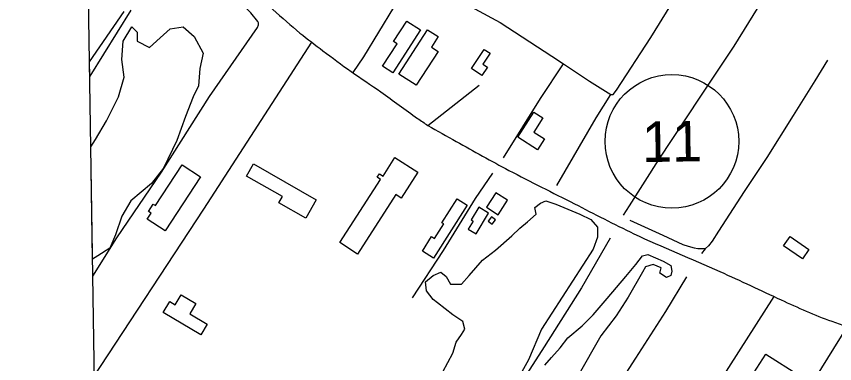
# Model space of a CAD drawing. Extents: x 3855477 to 3893699, y 299188 to 325115.
# Drawn here: x 3859445 to 3861465, y 310674 to 311532 of the extents above; entities that cross this region are included whole.
import ezdxf

# ---------------------------------------------------------------- set-up
doc = ezdxf.new("R2010")
doc.units = 0
for name, color, linetype in [('V-BLDG-OTLN', 7, 'Continuous'), ('V-GRID-FRAM', 7, 'Continuous'), ('V-ROAD-CNTR', 7, 'Continuous'), ('V-ROAD-IDEN', 7, 'Continuous'), ('V-SITE-VEGE', 7, 'Continuous'), ('V-TOPO-SHOR', 7, 'Continuous')]:
    doc.layers.add(name, color=color, linetype=linetype)

msp = doc.modelspace()

# ---------------------------------------------------------------- linework, layer by layer
at = {"layer": 'V-BLDG-OTLN'}
for points in [[(3860442.9, 311498.5), (3860374.1, 311392.1), (3860348.8, 311408.5), (3860384.9, 311464.3), (3860376.5, 311469.7), (3860409.2, 311520.3)], [(3860460.3, 311498.9), (3860486.7, 311481.9), (3860469.8, 311455.7), (3860486.2, 311445.2), (3860432.4, 311361.5), (3860389.6, 311389)], [(3860568.2, 311403.1), (3860599.6, 311450.3), (3860614.4, 311440.5), (3860596.6, 311413.8), (3860608, 311406.1), (3860594.4, 311385.7)], [(3860682.8, 311233.4), (3860722.1, 311295.2), (3860744.4, 311281), (3860722.2, 311246.1), (3860749, 311229), (3860731.9, 311202.1)], [(3860243.6, 310972.9), (3860344.1, 311129.2), (3860336.1, 311134.3), (3860341.7, 311143.1), (3860350.5, 311137.4), (3860379.8, 311182.9), (3860435.9, 311146.8), (3860394.8, 311082.9), (3860381.5, 311091.5), (3860287.2, 310944.9)], [(3859854.4, 311165.3), (3859899.7, 311135.8), (3859812.7, 311002.2), (3859768.3, 311031.1), (3859778, 311046), (3859771.7, 311050), (3859783.3, 311067.8), (3859788.7, 311064.3)], [(3860030.4, 311167.4), (3860185.6, 311078.9), (3860159.8, 311033.6), (3860093.4, 311071.5), (3860102, 311086.6), (3860013.2, 311137.3)], [(3860628.8, 311096), (3860606, 311060.3), (3860634.7, 311041.9), (3860657.5, 311077.7)], [(3860557.7, 311065.1), (3860474.8, 310934.4), (3860447.3, 310951.8), (3860470.2, 310987.8), (3860477.6, 310983.1), (3860500.4, 311019), (3860495.6, 311021.9), (3860532.9, 311080.8)], [(3860580.1, 310994.3), (3860610.9, 311046.1), (3860586.6, 311060.6), (3860567.8, 311029), (3860572.6, 311026.1), (3860560.6, 311006)], [(3860617.7, 311036.9), (3860609.7, 311026.4), (3860619.7, 311018.7), (3860627.7, 311029.2)], [(3861355.3, 310988.4), (3861401.5, 310955.7), (3861385.2, 310932.7), (3861339, 310965.4)], [(3859900.5, 310745.2), (3859807.8, 310800.1), (3859824, 310827.5), (3859837.5, 310819.5), (3859852, 310844.1), (3859888.6, 310822.5), (3859873.5, 310796.9), (3859916.2, 310771.6)], [(3861251, 310628.7), (3861294.9, 310697.6), (3861377.9, 310644.8), (3861333.9, 310575.6), (3861306.7, 310592.9), (3861291.5, 310569.1), (3861316.4, 310553.3), (3861305.3, 310535.8), (3861222.7, 310588.5), (3861234.3, 310606.7), (3861263.2, 310588.3), (3861278, 310611.6)]]:
    msp.add_lwpolyline(points, close=True, dxfattribs=at)
at = {"layer": 'V-GRID-FRAM'}
msp.add_lwpolyline([(3859445.3, 322797), (3891292.6, 323315.8), (3891596.8, 305135.9), (3859733.6, 304616.8), (3859445.3, 322797)], dxfattribs=at)
at = {"layer": 'V-ROAD-CNTR'}
for points in [[(3860276.2, 311393.5), (3860303, 311432.2), (3860377, 311553.8)], [(3860173.8, 311468), (3859907.5, 311055.6), (3859634.7, 310640.5)], [(3860461, 311262.2), (3860587.7, 311361.9)], [(3861315, 310839.8), (3861077.7, 310468.9)], [(3861496.1, 310765.8), (3861268, 310398.5), (3861240.4, 310360.1)]]:
    msp.add_lwpolyline(points, dxfattribs=at)
for points in [[(3859613.3, 311989.2), (3859816.5, 311793.7), (3859931.5, 311684.6), (3860011.9, 311608.3), (3860078.7, 311548.6), (3860145.2, 311490.6), (3860201.9, 311446.9), (3860271.3, 311395.8), (3860344.7, 311345.3), (3860435.6, 311279.7), (3860461, 311262.2)], [(3860461, 311262.2), (3860530.9, 311222.9), (3860661, 311151.4), (3860822.5, 311069), (3860969.5, 310994.9), (3861181.8, 310901.5), (3861332.6, 310831.7), (3861457.8, 310778.8), (3861532.1, 310756.1), (3861622.4, 310736.1), (3861704.6, 310721.1), (3861785.7, 310710.4), (3861858.8, 310704.3)]]:
    msp.add_spline(points, degree=3, dxfattribs=at)
at = {"layer": 'V-ROAD-IDEN'}
msp.add_circle((3861063.1, 311222.9), 165, dxfattribs=at)
msp.add_circle((3861063.1, 311222.9), 165, dxfattribs=at)
at = {"layer": 'V-SITE-VEGE'}
for p, q in [((3859727.5, 311546.7), (3859626.3, 311384.1)), ((3859625.7, 311419.7), (3859711.3, 311544)), ((3859708.6, 311470.9), (3859730.2, 311506.1)), ((3859730.2, 311506.1), (3859743.8, 311492.6)), ((3859824.9, 311500.7), (3859857.3, 311506.1)), ((3859857.3, 311506.1), (3859884.4, 311481.8)), ((3859743.8, 311492.6), (3859743.8, 311470.9)), ((3859800.5, 311479.1), (3859824.9, 311500.7)), ((3859705.9, 311425), (3859708.6, 311470.9)), ((3859743.8, 311470.9), (3859773.5, 311454.7)), ((3859773.5, 311454.7), (3859800.5, 311479.1)), ((3859884.4, 311481.8), (3859906, 311441.2)), ((3859711.3, 311381.7), (3859705.9, 311425)), ((3859906, 311441.2), (3859897.9, 311403.3)), ((3859626.3, 311384.1), (3859625.7, 311419.7)), ((3859897.9, 311403.3), (3859895.2, 311360)), ((3859697.8, 311333), (3859711.3, 311381.7)), ((3859895.2, 311360), (3859881.7, 311333)), ((3859668, 311273.5), (3859697.8, 311333)), ((3859881.7, 311333), (3859862.7, 311284.3)), ((3859862.7, 311284.3), (3859841.1, 311224.8)), ((3859641, 311227.5), (3859668, 311273.5)), ((3859629.1, 311209.5), (3859641, 311227.5)), ((3859841.1, 311224.8), (3859808.7, 311157.1)), ((3859633.5, 310932), (3859629.1, 311209.5)), ((3859808.7, 311157.1), (3859778.9, 311119.2)), ((3859778.9, 311119.2), (3859727.5, 311076)), ((3859727.5, 311076), (3859705.9, 311038.1)), ((3859705.9, 311038.1), (3859689.7, 310992.1)), ((3859689.7, 310992.1), (3859676.2, 310959.6)), ((3859646.4, 310940.7), (3859633.5, 310932)), ((3859676.2, 310959.6), (3859646.4, 310940.7))]:
    msp.add_line(p, q, dxfattribs=at)
for points in [[(3860498.2, 310653.9), (3860522.5, 310699.9), (3860530.6, 310727), (3860544.1, 310745.9), (3860552.3, 310759.4), (3860546.9, 310778.4), (3860522.5, 310794.6), (3860484.7, 310824.4), (3860473.8, 310832.5), (3860457.6, 310854.1), (3860454.9, 310875.8), (3860473.8, 310892), (3860492.8, 310900.1), (3860506.3, 310889.3), (3860517.1, 310870.4), (3860544.1, 310870.4), (3860563.1, 310892), (3860595.5, 310929.9), (3860628, 310954.2), (3860668.5, 310989.4), (3860687.5, 311008.3), (3860706.4, 311024.6), (3860728, 311043.5), (3860725.3, 311059.7), (3860738.8, 311070.6), (3860752.4, 311076), (3860776.7, 311067.8), (3860836.2, 311043.5), (3860863.2, 311030), (3860879.4, 311011), (3860879.4, 310986.7), (3860868.6, 310956.9), (3860741.5, 310759.4), (3860709.1, 310683.7), (3860692.9, 310653.9)], [(3860749.7, 310670.2), (3860765.9, 310689.1), (3860787.5, 310713.4), (3860806.4, 310737.8), (3860841.6, 310767.6), (3860868.6, 310794.6), (3860903.8, 310835.2), (3860949.7, 310889.3), (3860974.1, 310919.1), (3860990.3, 310940.7), (3861003.8, 310943.4), (3861041.7, 310927.2), (3861060.6, 310916.3), (3861063.3, 310902.8), (3861060.6, 310892), (3861049.8, 310886.6), (3861033.6, 310897.4), (3861036.3, 310910.9), (3861017.3, 310919.1), (3860998.4, 310913.6), (3860990.3, 310900.1), (3860955.2, 310837.9), (3860925.4, 310791.9), (3860887.6, 310743.2), (3860830.8, 310643.1)]]:
    msp.add_lwpolyline(points, dxfattribs=at)
at = {"layer": 'V-TOPO-SHOR'}
for points in [[(3862149, 312870.5), (3862093.3, 312784.2), (3862027.1, 312684.1), (3861933.1, 312545.9), (3861844, 312406.5), (3861755.6, 312272), (3861673.3, 312146.5), (3861631.9, 312086.2), (3861622, 312074.7), (3861612.8, 312063.9), (3861605.4, 312057.3), (3861597.4, 312046.5), (3861589.9, 312033.8), (3861552.8, 311980.1), (3861479.8, 311867.9), (3861424.8, 311783.4), (3861377.7, 311706.7), (3861288.1, 311575.8), (3861216.2, 311458.1), (3861133.4, 311334.5), (3861029.4, 311176.4), (3860957.6, 311063.5), (3860942.8, 311040.6)], [(3860514.3, 311585.1), (3860639.4, 311516.6), (3860766.8, 311433.3), (3860795.8, 311414.2), (3860860.2, 311371.6), (3860912.8, 311338.7), (3860915.8, 311338.6), (3860918.1, 311339.2), (3860926.5, 311349.7), (3861011, 311479.4), (3861099.1, 311623.2), (3861200.4, 311783.8), (3861289.6, 311919.4), (3861388.5, 312077.1), (3861502.2, 312240.6), (3861593.9, 312384.4), (3861713.7, 312566.6), (3861788, 312685.8), (3861807.8, 312714.5)], [(3859634.1, 310890.4), (3859693.5, 310984.7), (3859803.6, 311147.1), (3859922.3, 311333.5), (3860040.2, 311504), (3860043.2, 311511), (3860043.2, 311515.7), (3860040.9, 311519.3), (3860024.1, 311540.1), (3859912.9, 311651.4)], [(3860647.8, 311182.8), (3860738.5, 311328.9), (3860795.8, 311414.2)], [(3861446.9, 311423.5), (3861416.1, 311372.9), (3861362.5, 311287), (3861297.3, 311183), (3861241.3, 311099.5), (3861178.6, 311001.3), (3861162.9, 310976.7), (3861153.3, 310964.9), (3861146.5, 310958.8), (3861144.9, 310957.3), (3861136.5, 310946.2)], [(3860779.4, 311114.2), (3860876.3, 311280.8), (3860912.8, 311338.7)], [(3860422.7, 310836.9), (3860499.4, 310953.2), (3860578.6, 311082.3), (3860620.9, 311144.3)], [(3860959.2, 311028.1), (3861041.1, 310991.1), (3861090, 310968.6), (3861103.6, 310964.3), (3861118.3, 310960), (3861127.2, 310958.1), (3861146.5, 310958.8)], [(3860910.5, 310983.8), (3860839.8, 310861.2), (3860748.2, 310715.8), (3860662.2, 310582.4), (3860578, 310445.4), (3860509.3, 310342.9), (3860433.8, 310224), (3860362, 310110.5), (3860305.7, 310021.8), (3860284.1, 309993.5)], [(3861099.1, 310888.6), (3861047.2, 310803.3), (3860973.7, 310687.5), (3860903.1, 310578.7), (3860835, 310471.1), (3860763.2, 310358.3), (3860692.7, 310247.1), (3860625.8, 310143.1), (3860556.5, 310038.5), (3860505.2, 309957.3), (3860477.1, 309914.7)]]:
    msp.add_lwpolyline(points, dxfattribs=at)

# ---------------------------------------------------------------- texts
at = {"layer": 'V-ROAD-IDEN'}
msp.add_text('11', height=100, rotation=0.9334, dxfattribs=at).set_placement((3860989.9, 311171.7))

doc.saveas('drawing.dxf')
